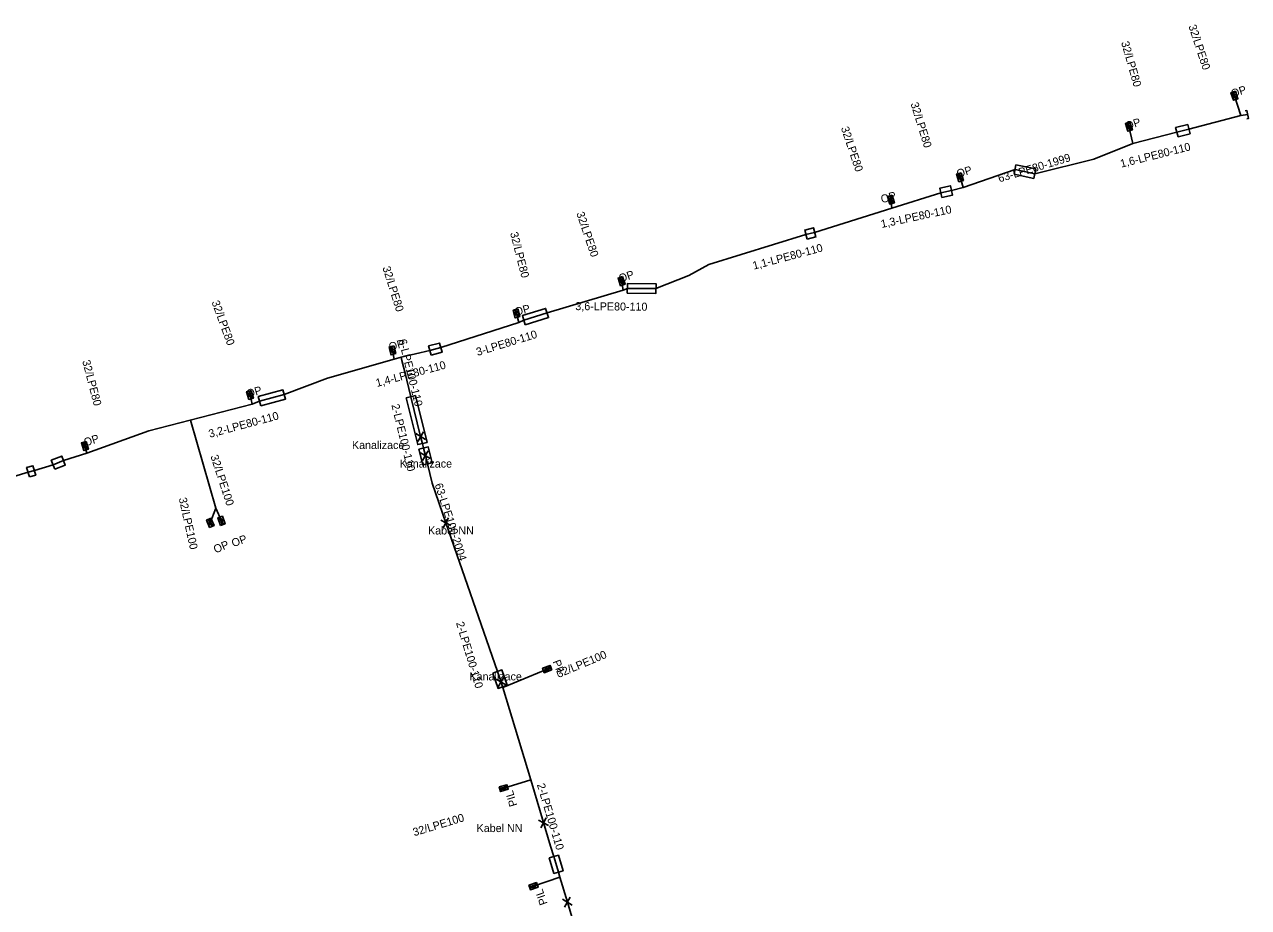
# Model space of a CAD drawing. Extents: x -762509 to -761250, y -1153000 to -1152256.
# Drawn here: x -761437.4 to -761284.5, y -1152400 to -1152289.7 of the extents above; entities that cross this region are included whole.
import ezdxf

# ---------------------------------------------------------------- set-up
doc = ezdxf.new("R2010")
doc.units = 0
for name, color, linetype in [('Vrstva 10', 7, 'Continuous'), ('Vrstva 21', 7, 'Continuous'), ('Vrstva 23', 7, 'Continuous'), ('Vrstva 29', 7, 'Continuous'), ('Vrstva 31', 7, 'Continuous'), ('Vrstva 32', 7, 'Continuous')]:
    doc.layers.add(name, color=color, linetype=linetype)

msp = doc.modelspace()

# ---------------------------------------------------------------- linework, layer by layer
at = {"layer": 'Vrstva 10'}
for p, q in [((-761388.517, -1152340.818), (-761387.302, -1152341.542)), ((-761388.272, -1152341.788), (-761387.548, -1152340.573)), ((-761387.927, -1152343.198), (-761386.712, -1152343.922)), ((-761387.682, -1152344.168), (-761386.958, -1152342.953)), ((-761384.42, -1152351.354), (-761385.08, -1152352.605)), ((-761385.375, -1152351.65), (-761384.124, -1152352.309)), ((-761378.477, -1152371.488), (-761377.262, -1152372.212)), ((-761378.232, -1152372.458), (-761377.508, -1152371.243)), ((-761371.927, -1152389.785), (-761373.173, -1152389.115)), ((-761372.215, -1152388.827), (-761372.885, -1152390.073)), ((-761370.187, -1152399.008), (-761368.972, -1152399.732)), ((-761369.942, -1152399.978), (-761369.218, -1152398.763))]:
    msp.add_line(p, q, dxfattribs=at)
at = {"layer": 'Vrstva 21'}
for points in [[(-761390.36, -1152331.28), (-761386.76, -1152330.44), (-761385.38, -1152330.07), (-761375.64, -1152326.92), (-761375.02, -1152326.63), (-761372.12, -1152325.74), (-761362.61, -1152322.88), (-761362.09, -1152322.66), (-761358.52, -1152322.69), (-761354.4, -1152321.06), (-761351.92, -1152319.67), (-761339.79, -1152315.95), (-761338.7, -1152315.66), (-761329.05, -1152312.63), (-761322.93, -1152310.71), (-761321.62, -1152310.43), (-761320.15, -1152310.04), (-761313.67, -1152307.82), (-761311.21, -1152308.33), (-761303.82, -1152306.5), (-761298.94, -1152304.56), (-761293.46, -1152303.15), (-761291.95, -1152302.77), (-761285.46, -1152301.06), (-761284.61, -1152300.93)], [(-761440.11, -1152346.61), (-761436.95, -1152345.64), (-761436.16, -1152345.41), (-761433.83, -1152344.71), (-761432.52, -1152344.19), (-761429.61, -1152343.24), (-761421.85, -1152340.47), (-761408.95, -1152337.12), (-761408.04, -1152336.77), (-761404.95, -1152335.94), (-761399.54, -1152333.87), (-761391.23, -1152331.49), (-761390.36, -1152331.28)], [(-761390.36, -1152331.28), (-761390.26, -1152331.68), (-761389.82, -1152333.44), (-761389.65, -1152334.14), (-761389.14, -1152336.2), (-761387.91, -1152341.18), (-761387.72, -1152341.93), (-761387.69, -1152342.05), (-761387.55, -1152342.62), (-761387.32, -1152343.56), (-761387.07, -1152344.59), (-761386.47, -1152347), (-761384.75, -1152351.98), (-761378.33, -1152370.54), (-761377.87, -1152371.85), (-761377.67, -1152372.45), (-761377.63, -1152372.54), (-761374.16, -1152384.1), (-761373.71, -1152385.61), (-761371.68, -1152392.36), (-761371.28, -1152393.67), (-761371.04, -1152394.49), (-761370.7, -1152395.61), (-761370.52, -1152396.23), (-761369.58, -1152399.37), (-761366.15, -1152410.89)]]:
    msp.add_lwpolyline(points, dxfattribs=at)
at = {"layer": 'Vrstva 23'}
msp.add_lwpolyline([(-761284.703, -1152301.46), (-761284.507, -1152301.419), (-761284.714, -1152300.44), (-761284.909, -1152300.482)], dxfattribs=at)
at = {"layer": 'Vrstva 29'}
for points in [[(-761293.31, -1152303.73), (-761291.8, -1152303.35), (-761292.1, -1152302.19), (-761293.61, -1152302.57)], [(-761313.79, -1152308.41), (-761311.33, -1152308.92), (-761311.09, -1152307.74), (-761313.55, -1152307.23)], [(-761322.8, -1152311.3), (-761321.49, -1152311.02), (-761321.75, -1152309.84), (-761323.06, -1152310.12)], [(-761339.64, -1152316.53), (-761338.55, -1152316.24), (-761338.85, -1152315.08), (-761339.94, -1152315.37)], [(-761362.1, -1152323.26), (-761358.53, -1152323.29), (-761358.51, -1152322.09), (-761362.08, -1152322.06)], [(-761374.84, -1152327.2), (-761371.94, -1152326.31), (-761372.3, -1152325.17), (-761375.2, -1152326.06)], [(-761386.6, -1152331.02), (-761385.22, -1152330.65), (-761385.54, -1152329.49), (-761386.92, -1152329.86)], [(-761407.88, -1152337.35), (-761404.79, -1152336.52), (-761405.11, -1152335.36), (-761408.2, -1152336.19)], [(-761389.72, -1152336.34), (-761388.27, -1152342.19), (-761387.11, -1152341.91), (-761388.56, -1152336.06)], [(-761433.61, -1152345.27), (-761432.3, -1152344.75), (-761432.74, -1152343.63), (-761434.05, -1152344.15)], [(-761388.13, -1152342.76), (-761387.65, -1152344.73), (-761386.49, -1152344.45), (-761386.97, -1152342.48)], [(-761436.78, -1152346.22), (-761435.99, -1152345.99), (-761436.33, -1152344.83), (-761437.12, -1152345.06)], [(-761378.9, -1152370.74), (-761378.24, -1152372.65), (-761377.1, -1152372.25), (-761377.76, -1152370.34)], [(-761371.85, -1152393.84), (-761371.27, -1152395.78), (-761370.13, -1152395.44), (-761370.71, -1152393.5)]]:
    msp.add_lwpolyline(points, close=True, dxfattribs=at)
at = {"layer": 'Vrstva 31'}
for points in [[(-761285.46, -1152301.06), (-761286.27, -1152298.59)], [(-761298.94, -1152304.56), (-761299.44, -1152302.45)], [(-761320.15, -1152310.04), (-761320.54, -1152308.78)], [(-761329.05, -1152312.63), (-761329.17, -1152311.57)], [(-761362.61, -1152322.88), (-761362.81, -1152321.76)], [(-761375.64, -1152326.92), (-761375.93, -1152325.79)], [(-761391.23, -1152331.49), (-761391.44, -1152330.41)], [(-761408.95, -1152337.12), (-761409.22, -1152335.97)], [(-761416.64, -1152339.15), (-761413.48, -1152350.13)], [(-761429.61, -1152343.24), (-761429.84, -1152342.36)], [(-761413.48, -1152350.13), (-761414.18, -1152351.96)], [(-761413.48, -1152350.13), (-761412.79, -1152351.71)], [(-761377.63, -1152372.54), (-761376.23, -1152371.96), (-761374.54, -1152371.26), (-761372.11, -1152370.24)], [(-761374.16, -1152384.1), (-761377.53, -1152385.12)], [(-761370.52, -1152396.23), (-761373.82, -1152397.38)]]:
    msp.add_lwpolyline(points, dxfattribs=at)
at = {"layer": 'Vrstva 32'}
for p, q in [((-761286.228, -1152298.156), (-761286.561, -1152298.265)), ((-761286.498, -1152298.456), (-761286.166, -1152298.347)), ((-761286.385, -1152298.207), (-761286.322, -1152298.398)), ((-761286.374, -1152298.835), (-761286.041, -1152298.726)), ((-761299.398, -1152302.015), (-761299.731, -1152302.125)), ((-761299.668, -1152302.316), (-761299.336, -1152302.206)), ((-761299.555, -1152302.067), (-761299.492, -1152302.258)), ((-761299.544, -1152302.695), (-761299.211, -1152302.585)), ((-761320.49, -1152308.347), (-761320.824, -1152308.449)), ((-761320.766, -1152308.641), (-761320.431, -1152308.539)), ((-761320.647, -1152308.395), (-761320.589, -1152308.587)), ((-761320.649, -1152309.023), (-761320.314, -1152308.921)), ((-761329.118, -1152311.136), (-761329.453, -1152311.238)), ((-761329.395, -1152311.43), (-761329.06, -1152311.329)), ((-761329.279, -1152311.812), (-761328.944, -1152311.711)), ((-761329.276, -1152311.184), (-761329.218, -1152311.376)), ((-761362.77, -1152321.325), (-761363.102, -1152321.435)), ((-761363.039, -1152321.626), (-761362.707, -1152321.516)), ((-761362.927, -1152321.377), (-761362.863, -1152321.568)), ((-761362.914, -1152322.005), (-761362.582, -1152321.895)), ((-761375.867, -1152325.358), (-761376.205, -1152325.45)), ((-761376.152, -1152325.644), (-761375.814, -1152325.551)), ((-761376.027, -1152325.401), (-761375.973, -1152325.595)), ((-761376.046, -1152326.029), (-761375.709, -1152325.936)), ((-761391.374, -1152329.978), (-761391.712, -1152330.068)), ((-761391.66, -1152330.262), (-761391.322, -1152330.172)), ((-761391.533, -1152330.021), (-761391.481, -1152330.215)), ((-761391.557, -1152330.648), (-761391.219, -1152330.558)), ((-761409.167, -1152335.537), (-761409.502, -1152335.637)), ((-761409.445, -1152335.83), (-761409.109, -1152335.73)), ((-761409.331, -1152336.212), (-761408.996, -1152336.112)), ((-761409.325, -1152335.584), (-761409.268, -1152335.777)), ((-761429.793, -1152341.925), (-761430.127, -1152342.031)), ((-761430.066, -1152342.223), (-761429.733, -1152342.117)), ((-761429.951, -1152341.975), (-761429.89, -1152342.167)), ((-761429.946, -1152342.603), (-761429.612, -1152342.497)), ((-761414.173, -1152351.523), (-761414.496, -1152351.658)), ((-761414.325, -1152351.587), (-761414.248, -1152351.772)), ((-761412.691, -1152351.463), (-761413.021, -1152351.58)), ((-761414.418, -1152351.843), (-761414.095, -1152351.709)), ((-761414.265, -1152352.212), (-761413.942, -1152352.077)), ((-761412.558, -1152351.839), (-761412.888, -1152351.956)), ((-761412.821, -1152352.145), (-761412.491, -1152352.029)), ((-761412.666, -1152352.09), (-761412.733, -1152351.901)), ((-761371.674, -1152370.262), (-761371.797, -1152369.935)), ((-761372.359, -1152370.147), (-761372.235, -1152370.474)), ((-761371.985, -1152370.006), (-761371.862, -1152370.333)), ((-761371.732, -1152370.108), (-761371.92, -1152370.179)), ((-761377.964, -1152385.068), (-761377.862, -1152385.403)), ((-761377.916, -1152385.226), (-761377.724, -1152385.168)), ((-761377.67, -1152385.345), (-761377.771, -1152385.01)), ((-761377.288, -1152385.229), (-761377.39, -1152384.894)), ((-761374.256, -1152397.346), (-761374.14, -1152397.677)), ((-761374.201, -1152397.502), (-761374.011, -1152397.436)), ((-761373.951, -1152397.611), (-761374.066, -1152397.28)), ((-761373.574, -1152397.479), (-761373.689, -1152397.149))]:
    msp.add_line(p, q, dxfattribs=at)
for points in [[(-761286.141, -1152298.022), (-761285.829, -1152298.972), (-761286.399, -1152299.159), (-761286.711, -1152298.209), (-761286.141, -1152298.022)], [(-761286.135, -1152298.441), (-761286.373, -1152298.519), (-761286.415, -1152298.548), (-761286.437, -1152298.587), (-761286.44, -1152298.633), (-761286.431, -1152298.66), (-761286.402, -1152298.695), (-761286.362, -1152298.712), (-761286.311, -1152298.71), (-761286.072, -1152298.632)], [(-761286.041, -1152298.726), (-761286.001, -1152298.849), (-761286.004, -1152298.895), (-761286.014, -1152298.914), (-761286.041, -1152298.938), (-761286.089, -1152298.953), (-761286.125, -1152298.95), (-761286.144, -1152298.941), (-761286.174, -1152298.906), (-761286.214, -1152298.783)], [(-761299.311, -1152301.881), (-761298.999, -1152302.831), (-761299.569, -1152303.019), (-761299.881, -1152302.069), (-761299.311, -1152301.881)], [(-761299.305, -1152302.3), (-761299.543, -1152302.379), (-761299.585, -1152302.407), (-761299.607, -1152302.447), (-761299.61, -1152302.492), (-761299.601, -1152302.52), (-761299.572, -1152302.555), (-761299.531, -1152302.572), (-761299.48, -1152302.57), (-761299.242, -1152302.491)], [(-761299.211, -1152302.585), (-761299.17, -1152302.709), (-761299.174, -1152302.754), (-761299.184, -1152302.773), (-761299.211, -1152302.797), (-761299.259, -1152302.813), (-761299.294, -1152302.81), (-761299.314, -1152302.8), (-761299.343, -1152302.766), (-761299.384, -1152302.642)], [(-761320.399, -1152308.215), (-761320.107, -1152309.171), (-761320.681, -1152309.346), (-761320.973, -1152308.39), (-761320.399, -1152308.215)], [(-761320.402, -1152308.634), (-761320.642, -1152308.707), (-761320.685, -1152308.735), (-761320.707, -1152308.774), (-761320.711, -1152308.819), (-761320.703, -1152308.847), (-761320.674, -1152308.882), (-761320.634, -1152308.9), (-761320.583, -1152308.899), (-761320.343, -1152308.826)], [(-761320.314, -1152308.921), (-761320.277, -1152309.045), (-761320.281, -1152309.09), (-761320.291, -1152309.109), (-761320.319, -1152309.132), (-761320.367, -1152309.147), (-761320.402, -1152309.143), (-761320.422, -1152309.133), (-761320.451, -1152309.098), (-761320.489, -1152308.974)], [(-761329.027, -1152311.004), (-761328.738, -1152311.962), (-761329.312, -1152312.135), (-761329.602, -1152311.178), (-761329.027, -1152311.004)], [(-761329.031, -1152311.423), (-761329.271, -1152311.496), (-761329.314, -1152311.524), (-761329.337, -1152311.563), (-761329.341, -1152311.608), (-761329.333, -1152311.636), (-761329.304, -1152311.671), (-761329.264, -1152311.689), (-761329.213, -1152311.689), (-761328.973, -1152311.616)], [(-761328.944, -1152311.711), (-761328.907, -1152311.835), (-761328.911, -1152311.88), (-761328.922, -1152311.899), (-761328.949, -1152311.922), (-761328.997, -1152311.937), (-761329.033, -1152311.933), (-761329.052, -1152311.923), (-761329.081, -1152311.888), (-761329.119, -1152311.763)], [(-761362.683, -1152321.191), (-761362.369, -1152322.141), (-761362.938, -1152322.329), (-761363.252, -1152321.379), (-761362.683, -1152321.191)], [(-761362.676, -1152321.61), (-761362.914, -1152321.689), (-761362.956, -1152321.718), (-761362.978, -1152321.757), (-761362.981, -1152321.803), (-761362.972, -1152321.83), (-761362.942, -1152321.865), (-761362.902, -1152321.882), (-761362.851, -1152321.88), (-761362.613, -1152321.801)], [(-761362.582, -1152321.895), (-761362.541, -1152322.018), (-761362.544, -1152322.064), (-761362.554, -1152322.083), (-761362.581, -1152322.107), (-761362.629, -1152322.122), (-761362.664, -1152322.119), (-761362.684, -1152322.11), (-761362.714, -1152322.076), (-761362.754, -1152321.952)], [(-761375.773, -1152325.228), (-761375.509, -1152326.192), (-761376.087, -1152326.351), (-761376.352, -1152325.387), (-761375.773, -1152325.228)], [(-761375.788, -1152325.647), (-761376.03, -1152325.713), (-761376.074, -1152325.74), (-761376.097, -1152325.778), (-761376.103, -1152325.823), (-761376.095, -1152325.851), (-761376.067, -1152325.887), (-761376.028, -1152325.907), (-761375.977, -1152325.907), (-761375.735, -1152325.841)], [(-761375.709, -1152325.936), (-761375.674, -1152326.062), (-761375.68, -1152326.107), (-761375.691, -1152326.125), (-761375.719, -1152326.148), (-761375.767, -1152326.161), (-761375.803, -1152326.156), (-761375.822, -1152326.146), (-761375.85, -1152326.11), (-761375.884, -1152325.984)], [(-761391.279, -1152329.849), (-761391.021, -1152330.815), (-761391.6, -1152330.97), (-761391.858, -1152330.004), (-761391.279, -1152329.849)], [(-761391.296, -1152330.268), (-761391.539, -1152330.333), (-761391.583, -1152330.359), (-761391.606, -1152330.397), (-761391.612, -1152330.442), (-761391.605, -1152330.47), (-761391.577, -1152330.506), (-761391.538, -1152330.526), (-761391.487, -1152330.527), (-761391.244, -1152330.462)], [(-761391.219, -1152330.558), (-761391.185, -1152330.683), (-761391.191, -1152330.728), (-761391.203, -1152330.747), (-761391.231, -1152330.769), (-761391.279, -1152330.782), (-761391.315, -1152330.777), (-761391.334, -1152330.766), (-761391.361, -1152330.73), (-761391.395, -1152330.605)], [(-761409.076, -1152335.406), (-761408.79, -1152336.364), (-761409.365, -1152336.535), (-761409.651, -1152335.577), (-761409.076, -1152335.406)], [(-761409.081, -1152335.825), (-761409.322, -1152335.896), (-761409.365, -1152335.924), (-761409.388, -1152335.963), (-761409.392, -1152336.008), (-761409.384, -1152336.036), (-761409.355, -1152336.071), (-761409.315, -1152336.089), (-761409.264, -1152336.089), (-761409.024, -1152336.017)], [(-761408.996, -1152336.112), (-761408.959, -1152336.237), (-761408.963, -1152336.282), (-761408.974, -1152336.301), (-761409.002, -1152336.324), (-761409.049, -1152336.338), (-761409.085, -1152336.334), (-761409.105, -1152336.324), (-761409.133, -1152336.289), (-761409.17, -1152336.164)], [(-761429.704, -1152341.792), (-761429.403, -1152342.746), (-761429.975, -1152342.927), (-761430.276, -1152341.973), (-761429.704, -1152341.792)], [(-761429.703, -1152342.211), (-761429.942, -1152342.287), (-761429.985, -1152342.315), (-761430.007, -1152342.355), (-761430.01, -1152342.4), (-761430.002, -1152342.428), (-761429.973, -1152342.462), (-761429.932, -1152342.48), (-761429.882, -1152342.479), (-761429.642, -1152342.403)], [(-761429.612, -1152342.497), (-761429.573, -1152342.621), (-761429.577, -1152342.667), (-761429.587, -1152342.686), (-761429.615, -1152342.709), (-761429.662, -1152342.724), (-761429.698, -1152342.721), (-761429.718, -1152342.711), (-761429.747, -1152342.676), (-761429.786, -1152342.552)], [(-761414.096, -1152351.383), (-761413.711, -1152352.306), (-761414.265, -1152352.537), (-761414.65, -1152351.614), (-761414.096, -1152351.383)], [(-761412.906, -1152352.281), (-761413.239, -1152351.338), (-761412.673, -1152351.138), (-761412.34, -1152352.081), (-761412.906, -1152352.281)], [(-761413.021, -1152351.58), (-761413.065, -1152351.457), (-761413.063, -1152351.412), (-761413.052, -1152351.392), (-761413.026, -1152351.368), (-761412.979, -1152351.351), (-761412.943, -1152351.354), (-761412.923, -1152351.362), (-761412.893, -1152351.396), (-761412.85, -1152351.519)], [(-761412.921, -1152351.862), (-761412.685, -1152351.779), (-761412.643, -1152351.749), (-761412.622, -1152351.709), (-761412.62, -1152351.664), (-761412.63, -1152351.636), (-761412.66, -1152351.602), (-761412.701, -1152351.586), (-761412.752, -1152351.589), (-761412.988, -1152351.673)], [(-761414.057, -1152351.8), (-761414.289, -1152351.897), (-761414.329, -1152351.928), (-761414.347, -1152351.97), (-761414.347, -1152352.015), (-761414.336, -1152352.042), (-761414.304, -1152352.074), (-761414.262, -1152352.088), (-761414.211, -1152352.082), (-761413.98, -1152351.986)], [(-761413.942, -1152352.077), (-761413.892, -1152352.197), (-761413.891, -1152352.242), (-761413.9, -1152352.262), (-761413.925, -1152352.288), (-761413.971, -1152352.307), (-761414.007, -1152352.307), (-761414.028, -1152352.299), (-761414.06, -1152352.267), (-761414.11, -1152352.147)], [(-761371.536, -1152370.344), (-761372.471, -1152370.697), (-761372.683, -1152370.136), (-761371.748, -1152369.782), (-761371.536, -1152370.344)], [(-761372.235, -1152370.474), (-761372.357, -1152370.52), (-761372.402, -1152370.519), (-761372.422, -1152370.509), (-761372.446, -1152370.483), (-761372.464, -1152370.436), (-761372.463, -1152370.401), (-761372.454, -1152370.38), (-761372.421, -1152370.35), (-761372.299, -1152370.304)], [(-761371.954, -1152370.368), (-761372.043, -1152370.133), (-761372.073, -1152370.092), (-761372.114, -1152370.072), (-761372.159, -1152370.071), (-761372.187, -1152370.082), (-761372.22, -1152370.112), (-761372.235, -1152370.153), (-761372.231, -1152370.204), (-761372.142, -1152370.439)], [(-761378.096, -1152384.977), (-761377.139, -1152384.688), (-761376.965, -1152385.262), (-761377.922, -1152385.552), (-761378.096, -1152384.977)], [(-761377.677, -1152384.981), (-761377.604, -1152385.221), (-761377.576, -1152385.264), (-761377.537, -1152385.287), (-761377.492, -1152385.291), (-761377.464, -1152385.282), (-761377.429, -1152385.254), (-761377.411, -1152385.214), (-761377.412, -1152385.163), (-761377.484, -1152384.923)], [(-761377.39, -1152384.894), (-761377.265, -1152384.857), (-761377.22, -1152384.861), (-761377.201, -1152384.872), (-761377.178, -1152384.899), (-761377.164, -1152384.947), (-761377.167, -1152384.983), (-761377.177, -1152385.002), (-761377.212, -1152385.031), (-761377.337, -1152385.068)], [(-761374.391, -1152397.261), (-761373.447, -1152396.932), (-761373.249, -1152397.499), (-761374.194, -1152397.828), (-761374.391, -1152397.261)], [(-761373.972, -1152397.248), (-761373.89, -1152397.485), (-761373.86, -1152397.526), (-761373.82, -1152397.547), (-761373.775, -1152397.55), (-761373.748, -1152397.54), (-761373.713, -1152397.51), (-761373.697, -1152397.469), (-761373.7, -1152397.419), (-761373.782, -1152397.182)], [(-761373.689, -1152397.149), (-761373.566, -1152397.106), (-761373.521, -1152397.108), (-761373.502, -1152397.119), (-761373.477, -1152397.145), (-761373.461, -1152397.192), (-761373.463, -1152397.228), (-761373.472, -1152397.248), (-761373.506, -1152397.278), (-761373.629, -1152397.321)]]:
    msp.add_lwpolyline(points, dxfattribs=at)

# ---------------------------------------------------------------- texts
at = {"layer": 'Vrstva 10'}
for s, p in [('Kanalizace', (-761396.49, -1152342.74)), ('Kanalizace', (-761390.53, -1152345.06)), ('Kabel NN', (-761386.99, -1152353.42)), ('Kanalizace', (-761381.81, -1152371.66)), ('Kabel NN', (-761380.92, -1152390.61))]:
    msp.add_text(s, height=1, dxfattribs=at).set_placement(p)
at = {"layer": 'Vrstva 21'}
for s, rotation, p in [('63-LPE80-1999', 16.71016, (-761315.62, -1152309.43)), ('63-LPE100-2004', 287.85006, (-761386.17, -1152347.19))]:
    msp.add_text(s, height=1, rotation=rotation, dxfattribs=at).set_placement(p)
at = {"layer": 'Vrstva 29'}
for s, rotation, p in [('1,6-LPE80-110', 14.12549, (-761300.39, -1152307.58)), ('1,3-LPE80-110', 12.06488, (-761330.32, -1152315.12)), ('1,1-LPE80-110', 14.89869, (-761346.3, -1152320.33)), ('3,6-LPE80-110', 359.51853, (-761368.59, -1152325.38)), ('3-LPE80-110', 17.06107, (-761380.8, -1152331.12)), ('6-LPE100-110', 283.92096, (-761390.67, -1152329.13)), ('1,4-LPE80-110', 15.00891, (-761393.37, -1152334.99)), ('2-LPE100-110', 283.69357, (-761391.57, -1152337.24)), ('3,2-LPE80-110', 15.03523, (-761414.24, -1152341.34)), ('2-LPE100-110', 286.6723, (-761383.5, -1152364.48)), ('2-LPE100-110', 286.64504, (-761373.4, -1152384.68))]:
    msp.add_text(s, height=1, rotation=rotation, dxfattribs=at).set_placement(p)
at = {"layer": 'Vrstva 31'}
for s, rotation, p in [('32/LPE80', 288.15614, (-761292.02, -1152289.88)), ('32/LPE80', 288.15614, (-761292.02, -1152289.88)), ('32/LPE80', 286.00777, (-761300.43, -1152291.93)), ('32/LPE80', 286.00777, (-761300.43, -1152291.93)), ('32/LPE80', 287.19854, (-761326.73, -1152299.58)), ('32/LPE80', 287.19854, (-761326.73, -1152299.58)), ('32/LPE80', 288.61103, (-761335.43, -1152302.62)), ('32/LPE80', 288.61103, (-761335.43, -1152302.62)), ('32/LPE80', 288.76656, (-761368.48, -1152313.28)), ('32/LPE80', 288.76656, (-761368.48, -1152313.28)), ('32/LPE80', 284.39359, (-761376.75, -1152315.75)), ('32/LPE80', 284.39359, (-761376.75, -1152315.75)), ('32/LPE80', 287.42954, (-761392.69, -1152320.07)), ('32/LPE80', 287.42954, (-761392.69, -1152320.07)), ('32/LPE80', 290.0541, (-761414.04, -1152324.38)), ('32/LPE80', 290.0541, (-761414.04, -1152324.38)), ('32/LPE80', 284.64738, (-761430.19, -1152331.75)), ('32/LPE80', 284.64738, (-761430.19, -1152331.75)), ('32/LPE100', 288.08344, (-761414.18, -1152343.64)), ('32/LPE100', 288.08344, (-761414.18, -1152343.64)), ('32/LPE100', 282.52881, (-761418.13, -1152348.91)), ('32/LPE100', 282.52881, (-761418.13, -1152348.91)), ('32/LPE100', 22.77038, (-761370.67, -1152371.35)), ('32/LPE100', 22.77038, (-761370.67, -1152371.35)), ('32/LPE100', 16.83952, (-761388.71, -1152391.14)), ('32/LPE100', 16.83952, (-761388.71, -1152391.14))]:
    msp.add_text(s, height=1, rotation=rotation, dxfattribs=at).set_placement(p)
at = {"layer": 'Vrstva 32'}
for s, rotation, p in [('OP', 18.15614, (-761286.51, -1152298.84)), ('OP', 18.15614, (-761286.51, -1152298.84)), ('OP', 18.18923, (-761299.71, -1152302.89)), ('OP', 18.18923, (-761299.71, -1152302.89)), ('OP', 16.97242, (-761320.79, -1152308.85)), ('OP', 16.97242, (-761320.79, -1152308.85)), ('OP', 16.82279, (-761330.27, -1152312.04)), ('OP', 16.82279, (-761330.27, -1152312.04)), ('OP', 18.29126, (-761362.98, -1152321.94)), ('OP', 18.29126, (-761362.98, -1152321.94)), ('OP', 15.34046, (-761376.01, -1152326.11)), ('OP', 15.34046, (-761376.01, -1152326.11)), ('OP', 14.948, (-761391.74, -1152330.48)), ('OP', 14.948, (-761391.74, -1152330.48)), ('OP', 16.5768, (-761409.5, -1152336.35)), ('OP', 16.5768, (-761409.5, -1152336.35)), ('OP', 17.55444, (-761429.81, -1152342.42)), ('OP', 17.55444, (-761429.81, -1152342.42)), ('OP', 22.6468, (-761413.53, -1152355.79)), ('OP', 22.6468, (-761413.53, -1152355.79)), ('OP', 19.46587, (-761411.32, -1152355.01)), ('OP', 19.46587, (-761411.32, -1152355.01)), ('PIL', 290.69027, (-761371.44, -1152369.3)), ('PIL', 290.69027, (-761371.44, -1152369.3)), ('PIL', 106.83952, (-761375.82, -1152387.26)), ('PIL', 106.83952, (-761375.82, -1152387.26)), ('PIL', 109.21267, (-761372.04, -1152399.54)), ('PIL', 109.21267, (-761372.04, -1152399.54))]:
    msp.add_text(s, height=1, rotation=rotation, dxfattribs=at).set_placement(p)

doc.saveas('drawing.dxf')
